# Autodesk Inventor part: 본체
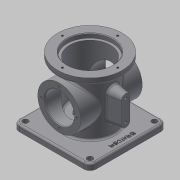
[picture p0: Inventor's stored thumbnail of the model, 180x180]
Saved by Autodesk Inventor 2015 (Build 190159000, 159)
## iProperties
Created: 2017-08
Part Number: 본체
Material: 알루미늄 6061
Document SubType Name: Modeling
Designer: mduedu
Density: 2.71 g/cm^3
Mass: 872.327 g
Surface Area: 642.238 cm^2
Volume: 321.892 cm^3
Appearance: 기본값
Author: mduedu
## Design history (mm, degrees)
sketch "스케치1"
  geometry: L1 (-62.5, -62.5)-(62.5, -62.5); L2 (62.5, -62.5)-(62.5, 62.5); L3 (62.5, 62.5)-(-62.5, 62.5); L4 (-62.5, 62.5)-(-62.5, -62.5); L5 (-62.5, -62.5)-(62.5, 62.5); L6 (62.5, -62.5)-(-62.5, 62.5); 1 further point
  constraints: 12 end point, 2 midpoint, 2 parallel, 1 horizontal, 1 perpendicular
  dimensions: "d232" = 125 distance of L3.end L2.end; "d233" = 125 distance of L2.end L1.end
extrude "돌출1" new body sketch "스케치1" distance "d5" = 10; taper "d6" = 0 deg
sketch "스케치2"
  geometry: C1 r 38 at (0, 0); 1 further point
  constraints: 1 centre point, 1 coincident
  dimensions: "d111" = 76 diameter of C1
extrude "돌출2" join sketch "스케치2" distance "d12" = 88; taper "d13" = 0 deg
sketch "스케치3"
  geometry: C1 r 52.5 at (0, 0); 1 further point
  constraints: 1 centre point, 1 coincident
  dimensions: "d114" = 105 diameter of C1
extrude "돌출3" join sketch "스케치3" distance "d19" = 10; taper "d20" = 0 deg
sketch "스케치4"
  geometry: C1 r 33 at (0, 0); 1 further point
  constraints: 1 centre point, 1 coincident
  dimensions: "d115" = 66 diameter of C1
extrude "돌출4" cut sketch "스케치4" distance "d26" = 86; taper "d27" = 0 deg
sketch "스케치5"
  geometry: C1 r 37 at (0, 0); 1 further point
  constraints: 1 centre point, 1 coincident
  dimensions: "d116" = 74 diameter of C1
extrude "돌출5" cut sketch "스케치5" distance "d29" = 7; taper "d30" = 0 deg
node "작업 평면1"
sketch "스케치18"
  geometry: L1 (-62.5, 0)-(62.5, 0) reference; C1 r 35 at (0, 54); 1 further point
  constraints: 1 centre point, 1 vertical alignment
  dimensions: "d118" = 70 diameter of C1; "d234" = 54 distance from line of C1.centre L1
extrude "돌출9" join sketch "스케치18" stored distance "d120" = 10; taper "d121" = 0 deg
hole "구멍8" diameter "d124" = 48; stored, may be unused: countersink angle "d128" = 90 deg, drill point angle "d130" = 118 deg; dims "d122" = 10, "d123" = 10, "d125" = 6, "d126" = 4, "d127" = 2, "d129" = 8
sketch "스케치9"
  geometry: C1 r 33 at (0, 0); 1 further point
  constraints: 1 centre point, 1 coincident
  dimensions: "d131" = 66 diameter of C1
extrude "돌출8" cut sketch "스케치9" distance "d43" = 16; taper "d44" = 0 deg
node "작업 평면2"
fillet "모깎기9" dims "d137" = 3
fillet "모깎기10" dims "d138" = 3
chamfer "모따기2" distance "d139" = 1; stored, may be unused: second distance "d140" = 2, angle "d141" = 45 deg
fillet "모깎기11" dims "d142" = 3
fillet "모깎기12" dims "d143" = 3
fillet "모깎기13" dims "d144" = 3
node "작업 평면3"
sketch "스케치20"
  geometry: L1 (108, -52.5)-(108, 52.5) reference; L2 (37, 7)-(71, 7); L3 (37, -7)-(71, -7); L4 (0, -33)-(0, 33) reference; A1 r 7 centre (37, 0) between (37, 7) and (37, -7); A2 r 7 centre (71, 0) between (71, 7) and (71, -7); 1 further point
  constraints: 4 end point, 4 point on circle, 3 tangent, 2 centre point, 2 horizontal alignment, 1 parallel, 1 perpendicular
  dimensions: "d203" = 14 diameter of A1; "d206" = 30 distance edge to line of A2 L1; "d207" = 48 dimension on A2 A1 (derived); "d236" = 30 distance edge to line of A1 L4
extrude "돌출10" join sketch "스케치20" stored distance "d152" = 10; taper "d153" = 10 deg
sketch "스케치21"
  geometry: C1 r 7 at (0, 71) reference; C2 r 7 at (0, 37) reference; 3 further points
  constraints: 2 coincident
hole "구멍12" sketch "스케치21" at (0, 71), (0, 37) diameter "d219" = 4.134; stored, may be unused: countersink angle "d223" = 90 deg, drill point angle "d225" = 118 deg; dims "d220" = 6, "d221" = 4, "d222" = 2, "d224" = 8
fillet "모깎기18" dims "d229" = 3
sketch "스케치23"
  geometry: C1 r 20 at (0, 0); 1 further point
  constraints: 1 centre point, 1 coincident
  dimensions: "d168" = 40 diameter of C1
extrude "돌출12" cut sketch "스케치23" stored distance "d169" = 148.25; taper "d170" = 0 deg
sketch "스케치28"
  geometry: L1 (62.5, -62.5)-(62.5, 62.5) reference; 2 further points
  constraints: 1 horizontal alignment, 1 other
  dimensions: "d238" = 10 distance from line of point (52.5, 0) L1
feature "엠보싱4" sketch "스케치28" dims "d239" = 0.5, "d240" = 0
sketch "스케치25" dims "d178" = 58
  geometry: C1 r 35 at (0, 0) reference; 3 further points
  constraints: 2 vertical alignment, 1 coincident, 2 other
hole "구멍10" sketch "스케치25" at (0, 29) diameter "d179" = 3.242; stored, may be unused: countersink angle "d183" = 90 deg, drill point angle "d185" = 118 deg; dims "d180" = 4, "d181" = 4, "d182" = 2, "d184" = 6
sketch "스케치26" dims "d189" = 90
  geometry: 3 further points
  constraints: 2 vertical alignment, 1 coincident, 2 other
hole "구멍11" sketch "스케치26" at (0, 45) diameter "d190" = 3.242; stored, may be unused: countersink angle "d194" = 90 deg, drill point angle "d196" = 118 deg; dims "d191" = 4, "d192" = 4, "d193" = 2, "d195" = 6
chamfer "모따기4" distance "d200" = 1; stored, may be unused: second distance "d201" = 2, angle "d202" = 45 deg
fillet "모깎기19" dims "d241" = 10
sketch "스케치29"
  geometry: A1 r 10 centre (-52.5, 52.5) between (-52.5, 62.5) and (-62.5, 52.5) reference; A2 r 10 centre (52.5, 52.5) between (62.5, 52.5) and (52.5, 62.5) reference; A3 r 10 centre (52.5, -52.5) between (52.5, -62.5) and (62.5, -52.5) reference; A4 r 10 centre (-52.5, -52.5) between (-62.5, -52.5) and (-52.5, -62.5) reference; 5 further points
  constraints: 4 coincident
hole "구멍13" sketch "스케치29" at (-52.5, 52.5), (52.5, 52.5), (52.5, -52.5), (-52.5, -52.5) diameter "d242" = 9; stored, may be unused: countersink angle "d246" = 90 deg, drill point angle "d248" = 118 deg; dims "d243" = 6, "d244" = 4, "d245" = 2, "d247" = 8
fillet "모깎기20" dims "d249" = 3
node "솔리드1"
mirror "대칭2"
pattern_circular "원형 패턴1" dims angle "d187" = 360 deg
mirror "대칭3"
pattern_circular "원형 패턴2" dims angle "d198" = 360 deg
other parameters: "d147" = 58
